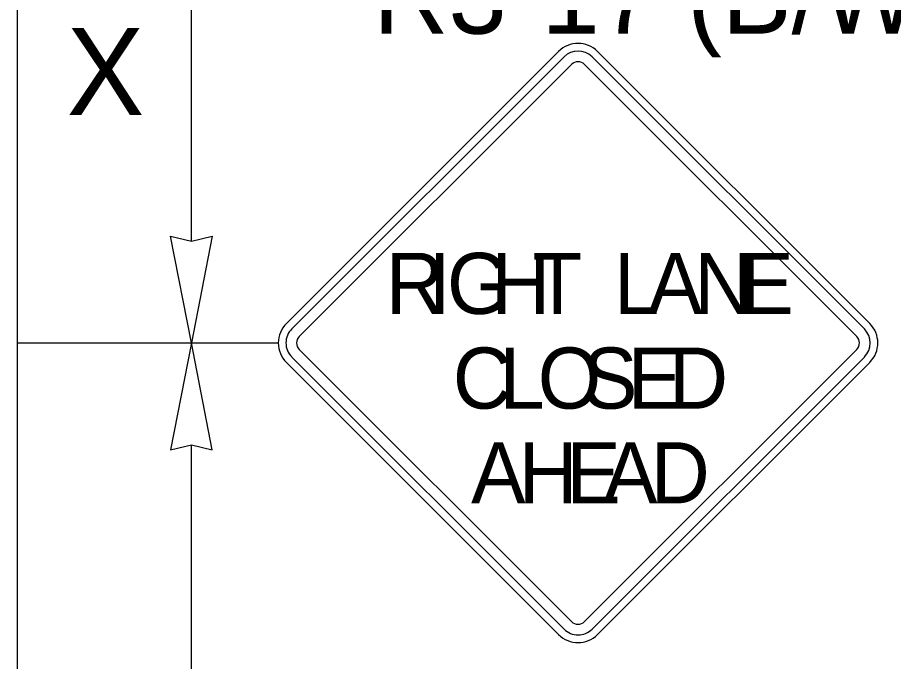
# Model space of a CAD drawing. Extents: x 99958 to 100176, y 99935 to 100011.
# Drawn here: x 100044.232 to 100045.038, y 99972.748 to 99973.341 of the extents above; entities that cross this region are included whole.
import ezdxf

# ---------------------------------------------------------------- set-up
doc = ezdxf.new("R2010")
doc.units = 0
for name, color, linetype in [('RD_ED_ShoulderPavedEdge', 7, 'Continuous'), ('TR_SN_ConstructionSigns', 7, 'Continuous'), ('TR_WZ_WorkZoneDetails', 7, 'Continuous'), ('TR_WZ_WorkZoneTextCurrent', 7, 'Continuous')]:
    doc.layers.add(name, color=color, linetype=linetype)

msp = doc.modelspace()

# ---------------------------------------------------------------- linework, layer by layer
at = {"layer": 'RD_ED_ShoulderPavedEdge'}
msp.add_lwpolyline([(100044.23194, 99971.9059), (100044.23194, 99973.67245)], dxfattribs=at)
at = {"layer": 'TR_SN_ConstructionSigns'}
for p, q in [((100044.72994, 99973.31008), (100044.47936, 99973.0595)), ((100044.73491, 99973.30511), (100044.48433, 99973.05453)), ((100045.01134, 99973.05453), (100044.76076, 99973.30511)), ((100045.01632, 99973.0595), (100044.76574, 99973.31008)), ((100044.49129, 99973.04757), (100044.74187, 99973.29815)), ((100044.7538, 99973.29815), (100045.00438, 99973.04757)), ((100044.74187, 99972.78505), (100044.49129, 99973.03563)), ((100045.00438, 99973.03563), (100044.7538, 99972.78505)), ((100044.47936, 99973.0237), (100044.72994, 99972.77312)), ((100044.48433, 99973.02867), (100044.73491, 99972.77809)), ((100044.76076, 99972.77809), (100045.01134, 99973.02867)), ((100044.76574, 99972.77312), (100045.01632, 99973.0237))]:
    msp.add_line(p, q, dxfattribs=at)
for centre, radius, start, end in [((100044.74784, 99973.29218), 0.02531, 45, 135), ((100044.74784, 99973.29218), 0.01828, 45, 135), ((100044.74784, 99973.29218), 0.00844, 45, 135), ((100044.49726, 99973.0416), 0.02531, 135, 225.00001), ((100044.49726, 99973.0416), 0.01828, 135, 225.00001), ((100044.99842, 99973.0416), 0.01828, 315.00002, 45), ((100044.99842, 99973.0416), 0.02531, 315.00001, 45.00001), ((100044.49726, 99973.0416), 0.00844, 135, 225.00001), ((100044.99842, 99973.0416), 0.00844, 315.00002, 45), ((100044.74784, 99972.79102), 0.00844, 225.00001, 315.00002), ((100044.74784, 99972.79102), 0.02531, 225.00001, 315.00001), ((100044.74784, 99972.79102), 0.01828, 225.00001, 315.00002)]:
    msp.add_arc(centre, radius, start, end, dxfattribs=at)
at = {"layer": 'TR_WZ_WorkZoneDetails'}
for p, q in [((100044.39194, 99973.13533), (100044.39194, 99973.44787)), ((100044.23194, 99973.0416), (100044.47194, 99973.0416)), ((100044.39194, 99972.38533), (100044.39194, 99972.94787))]:
    msp.add_line(p, q, dxfattribs=at)
for points in [[(100044.39194, 99973.0416), (100044.37267, 99973.13988), (100044.39194, 99973.13533), (100044.41122, 99973.13988)], [(100044.39194, 99973.0416), (100044.37267, 99972.94332), (100044.39194, 99972.94787), (100044.41122, 99972.94332)]]:
    msp.add_lwpolyline(points, close=True, dxfattribs=at)

# ---------------------------------------------------------------- texts
at = {"layer": 'TR_SN_ConstructionSigns'}
msp.add_text('R3-17 (B/W)', height=0.072, rotation=360, dxfattribs=at).set_placement((100044.55905, 99973.32645))
for s, p in [('R', (100044.57065, 99973.06832)), ('I', (100044.61001, 99973.06832)), ('G', (100044.62712, 99973.06832)), ('H', (100044.66787, 99973.06832)), ('T', (100044.70584, 99973.06832)), ('L', (100044.78074, 99973.06832)), ('A', (100044.8122, 99973.06832)), ('N', (100044.85467, 99973.06832)), ('E', (100044.89634, 99973.06832)), ('C', (100044.63252, 99972.98113)), ('O', (100044.71071, 99972.98113)), ('S', (100044.75234, 99972.98113)), ('L', (100044.67527, 99972.98113)), ('E', (100044.7934, 99972.98113)), ('D', (100044.83165, 99972.98113)), ('A', (100044.6494, 99972.89394)), ('H', (100044.69327, 99972.89394)), ('E', (100044.73715, 99972.89394)), ('A', (100044.7709, 99972.89394)), ('D', (100044.81477, 99972.89394))]:
    msp.add_text(s, height=0.05625, dxfattribs=at).set_placement(p)
at = {"layer": 'TR_WZ_WorkZoneTextCurrent'}
msp.add_text('X', height=0.08, dxfattribs=at).set_placement((100044.27723, 99973.2516))

doc.saveas('drawing.dxf')
